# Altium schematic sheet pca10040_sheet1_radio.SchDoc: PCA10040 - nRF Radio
size A4; Revision: 1.1.0; SheetNumber: 1; SheetTotal: 5; DrawnBy: KJP; ProjectNumber: 4397; PCBRevision: 0071KJP; DocumentSize: A4; PCAName: PCA10040; PCBNumber: 400150
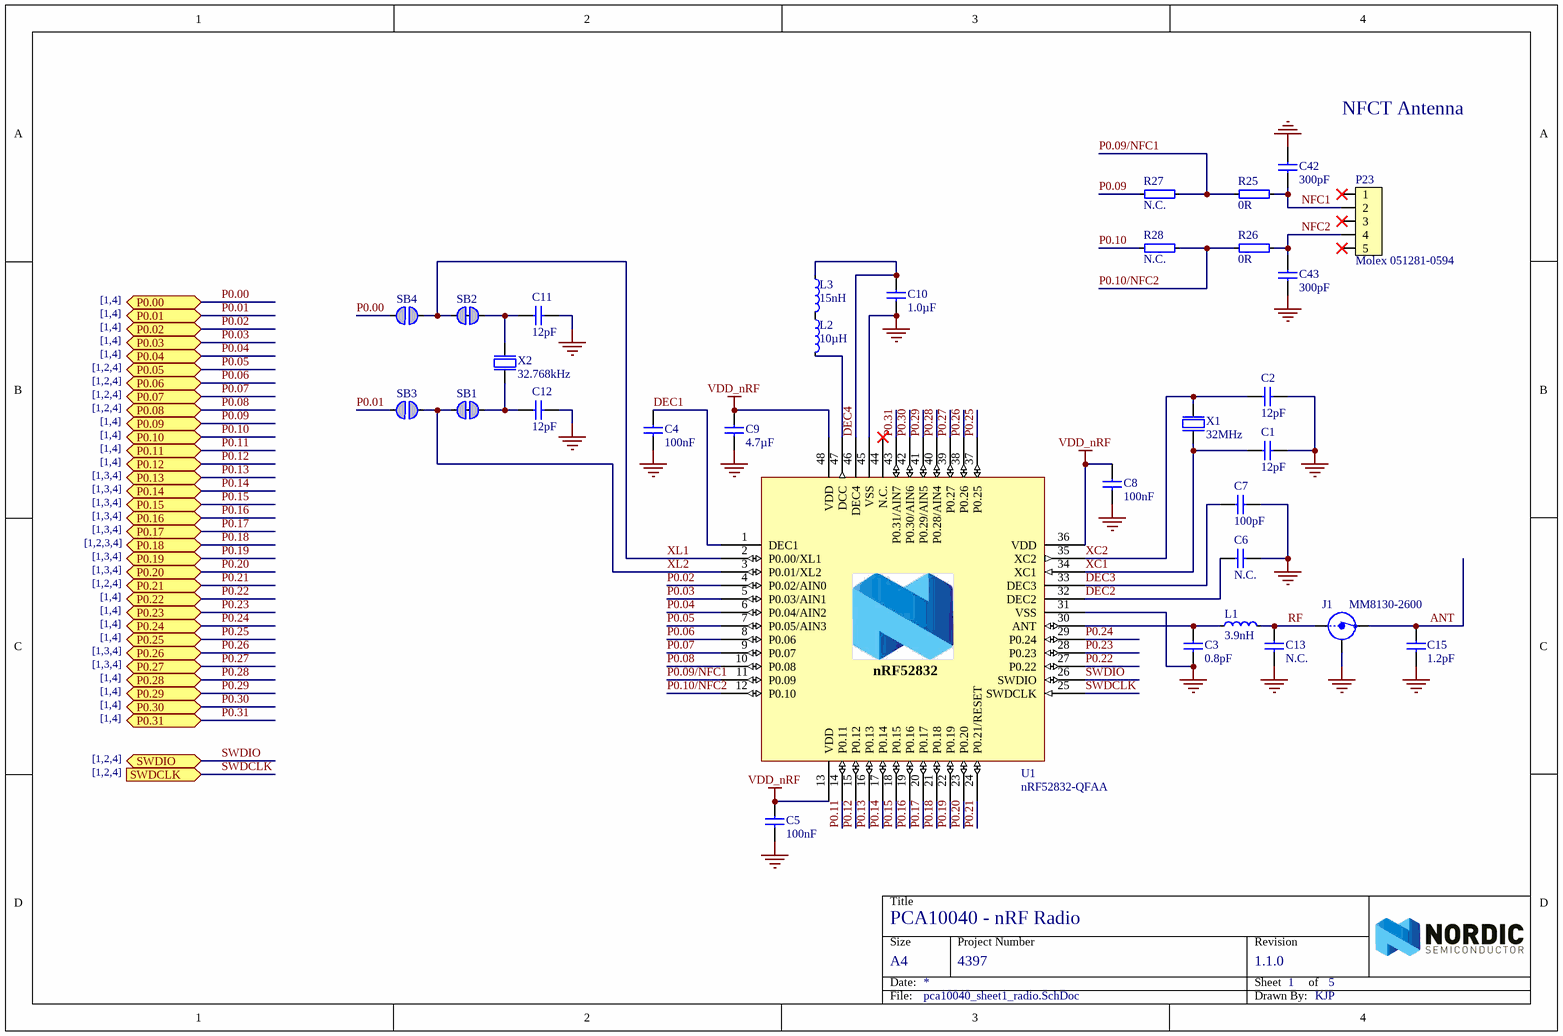
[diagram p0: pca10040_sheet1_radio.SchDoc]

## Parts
C1  12pF  [CAPC1005X04L]
C2  12pF  [CAPC1005X04L]
C3  0.8pF  [CAPC1005X04L]
C4  100nF  [CAPC1005X04L]
C5  100nF  [CAPC1005X04L]
C6  N.C.  [CAPC1005X04L]
C7  100pF  [CAPC1005X04L]
C8  100nF  [CAPC1005X04L]
C9  4.7µF  [CAPC1608X06L]
C10  1.0µF  [CAPC1608X06L]
C11  12pF  [CAPC1005X04L]
C12  12pF  [CAPC1005X04L]
C13  N.C.  [CAPC1005X04L]
C15  1.2pF  [CAPC1005X04L]
C42  300pF  [CAPC1005X04L]
C43  300pF  [CAPC1005X04L]
J1  MM8130-2600  [COAXIAL-SWF]
L1  3.9nH  [INDC1005X04L]
L2  10µH  [INDC1608X06L]
L3  15nH  [INDC1005X04L]
P23  Molex 051281-0594  [Molex 051281-0594]
R25  0R  [RESC1005X04L]
R26  0R  [RESC1005X04L]
R27  N.C.  [RESC1005X04L]
R28  N.C.  [RESC1005X04L]
SB1  Solderbridge  [Solderbridge_Shorted]  (value not drawn)  (net tie, no BOM)
SB2  Solderbridge  [Solderbridge_Shorted]  (value not drawn)  (net tie, no BOM)
SB3  Solderbridge  [Solderbridge]  (value not drawn)  (no BOM)
SB4  Solderbridge  [Solderbridge]  (value not drawn)  (no BOM)
U1  nRF52832-QFAA  [QFN40P600X600X90-48N]
X1  32MHz  [BT-XTAL_2016]
X2  32.768kHz  [XTAL_3215]

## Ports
P0.00 (bidir), P0.01 (bidir), P0.02 (bidir), P0.03 (bidir), P0.04 (bidir), P0.05 (bidir), P0.06 (bidir), P0.07 (bidir), P0.08 (bidir), P0.09 (bidir), P0.10 (bidir), P0.11 (bidir), P0.12 (bidir), P0.13 (bidir), P0.14 (bidir), P0.15 (bidir), P0.16 (bidir), P0.17 (bidir), P0.18 (bidir), P0.19 (bidir), P0.20 (bidir), P0.21 (bidir), P0.22 (bidir), P0.23 (bidir), P0.24 (bidir), P0.25 (bidir), P0.26 (bidir), P0.27 (bidir), P0.28 (bidir), P0.29 (bidir), P0.30 (bidir), P0.31 (bidir), SWDCLK (in), SWDIO (bidir)

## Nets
GND: C1.2 C2.2 C3.1 C4.2 C5.2 C6.2 C7.2 C8.2 C9.2 C10.1 C11.1 C12.1 C13.2 C15.2 C42.2 C43.1 J1.2(Shield) U1.31(VSS) U1.45(VSS) U1.49(GND) X1.2(GND) X1.4(GND)
VDD_nRF: C5.1 C8.1 C9.1 U1.13(VDD) U1.36(VDD) U1.48(VDD)
ANT: C15.1 J1.3(OUT)
DEC1: C4.1 U1.1(DEC1)
DEC2: C6.1 U1.32(DEC2)
DEC3: C7.1 U1.33(DEC3)
DEC4: C10.2 L3.1 U1.46(DEC4)
NFC1: C42.1 P23.2 R25.1
NFC2: C43.2 P23.4 R26.1
P0.00: SB4.2 ; port P0.00
P0.01: SB3.2 ; port P0.01
P0.02: U1.4(P0.02/AIN0) ; port P0.02
P0.03: U1.5(P0.03/AIN1) ; port P0.03
P0.04: U1.6(P0.04/AIN2) ; port P0.04
P0.05: U1.7(P0.05/AIN3) ; port P0.05
P0.06: U1.8(P0.06) ; port P0.06
P0.07: U1.9(P0.07) ; port P0.07
P0.08: U1.10(P0.08) ; port P0.08
P0.09: R27.1 ; port P0.09
P0.09/NFC1: R25.2 R27.2 U1.11(P0.09)
P0.10: R28.1 ; port P0.10
P0.10/NFC2: R26.2 R28.2 U1.12(P0.10)
P0.11: U1.14(P0.11) ; port P0.11
P0.12: U1.15(P0.12) ; port P0.12
P0.13: U1.16(P0.13) ; port P0.13
P0.14: U1.17(P0.14) ; port P0.14
P0.15: U1.18(P0.15) ; port P0.15
P0.16: U1.19(P0.16) ; port P0.16
P0.17: U1.20(P0.17) ; port P0.17
P0.18: U1.21(P0.18) ; port P0.18
P0.19: U1.22(P0.19) ; port P0.19
P0.20: U1.23(P0.20) ; port P0.20
P0.21: U1.24(P0.21/RESET) ; port P0.21
P0.22: U1.27(P0.22) ; port P0.22
P0.23: U1.28(P0.23) ; port P0.23
P0.24: U1.29(P0.24) ; port P0.24
P0.25: U1.37(P0.25) ; port P0.25
P0.26: U1.38(P0.26) ; port P0.26
P0.27: U1.39(P0.27) ; port P0.27
P0.28: U1.40(P0.28/AIN4) ; port P0.28
P0.29: U1.41(P0.29/AIN5) ; port P0.29
P0.30: U1.42(P0.30/AIN6) ; port P0.30
P0.31: U1.43(P0.31/AIN7) ; port P0.31
RF: C13.1 J1.1(IN) L1.2
SWDCLK: U1.25(SWDCLK) ; port SWDCLK
SWDIO: U1.26(SWDIO) ; port SWDIO
XC1: C1.1 U1.34(XC1) X1.1(inp)
XC2: C2.1 U1.35(XC2) X1.3(out)
XL1: SB2.2 SB4.1 U1.2(P0.00/XL1)
XL2: SB1.2 SB3.1 U1.3(P0.01/XL2)
NetC3_2: C3.2 L1.1 U1.30(ANT)
NetC11_2: C11.2 SB2.1 X2.1(inp)
NetC12_2: C12.2 SB1.1 X2.2(out)
NetL2_1: L2.1 L3.2
NetL2_2: L2.2 U1.47(DCC)

Not connected (* = marked no-connect by the designer): P23 1* 3* 5*; U1 44(N.C.)*

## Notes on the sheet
- NFCT Antenna
- [1,4]
- [1,2,4]
- [1,3,4]
- [1,2,3,4]

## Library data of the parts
C1 C2 C11 C12 = C0402-12p: Capacitor, NP0, ±2%; Note: 50V; Artikkelnr Noca: 20029159; Artikkelnr Simpro: N.A.
C3 = C0402-0.8p: Capacitor, NP0, ±5%; Note: 50V; Artikkelnr Noca: 20029147; Artikkelnr Simpro: N.A.
C4 C5 C8 = C0402-100n: Capacitor, X7R, ±10%; Note: 16V; Artikkelnr Noca: 20039200; Artikkelnr Simpro: N.A.
C6 C13 = C0402-N.C.: Not mounted; Note: Chip Cap; Artikkelnr Noca: N.A.
C7 = C0402-100p: Capacitor, NP0, ±5%; Note: 50V; Artikkelnr Noca: 20029135; Artikkelnr Simpro: N.A.
C9 = C0603-4µ7: Capacitor, X5R, ±10%; Note: 6.3V; Artikkelnr Noca: 20069060; Artikkelnr Simpro: N.A.
C10 = C0603-1µ0: Capacitor, X7R, ±10%; Note: 16V; Artikkelnr Noca: 20039335; Artikkelnr Simpro: N.A.
C15 = C0402-1.2p: Capacitor, NP0, ±0.1pF; Note: 50V; Artikkelnr Noca: 20029157; Artikkelnr Simpro: N.A.
C42 C43 = C0402-300p: Capacitor, NP0, ±5%; Note: 50V; Artikkelnr Noca: N.A.
J1 = MM8130-2600: Coaxial Connector with Switch; Manufacturer: Murata; 2nd source part number: 81-MM8130-2600RA2; Artikkelnr Noca: 55029011; Artikkelnr Simpro: N.A.
L1 = L0402-3n9: Inductor, 170mA, ±0.1nH; Manufacturer: Murata; Manufacturer Part Number: LQP15MN3N9B02D; Note: High frequency chip inductor ±5%; Artikkelnr Noca: 33029151; Artikkelnr Simpro: N.A.
L2 = L0603-10µ: Inductor, 80mA, ±10%; Manufacturer: Taiyo Yuden; Manufacturer Part Number: LBMF1608T100K; 2nd source part number: 178-6105; Note: LBMF1608T100K 10µH 80mA 0603; Artikkelnr Noca: 33029314; Artikkelnr Simpro: N.A.
L3 = L0402-15n: Inductor, 320mA, ±5%; Manufacturer: Taiyo Yuden; Manufacturer Part Number: HK100515NJ-T; 2nd source part number: 658-1328; Note: High frequency chip inductor ±10%; Artikkelnr Noca: 33029323; Artikkelnr Simpro: N.A.
P23 = Molex 051281-0594: CONN FFC FPC 5POS 0.50MM R/A; Artikkelnr Noca: N.A.
R25 R26 = R0402-0R: Resistor, ±5%, 0.063W; Note: Chip Res 5%; Artikkelnr Noca: 27049000; Artikkelnr Simpro: N.A.
R27 R28 = R0402-N.C.: Not mounted; Note: Chip Res; Artikkelnr Noca: N.A.
SB1 SB2 = Solderbridge Shorted: Shorted Solderbridge; Artikkelnr Noca: N.A.
SB3 SB4 = Solderbridge: Artikkelnr Noca: N.A.
U1 = nRF52832-QFAA: Multi-protocol Bluetooth Low Energy and 2.4GHz proprietary system-on-chip; Manufacturer: Nordic Semiconductor; Artikkelnr Noca: N.A.
X1 = XTAL_SMD2016_32MHz_8pF_Epson: XTAL SMD 2016, 32MHz, Cl=8pF, Tol: ±10ppm, Stab: ±10ppm; Manufacturer: Epson Toyocom; Manufacturer Part Number: Q22FA12800025; Note: XTAL SMD 32.000MHz; Artikkelnr Noca: N.A.
X2 = XTAL_FC-135 32.768k: EPSON TOYOCOM - FC-135 32.768KHZ ±20PPM,9.0PF - CRYSTAL, SM, WATCH; 2nd source part number: 127-8037; Note: XTAL SMD 32.768kHz, 3215; Artikkelnr Noca: 22019091; Artikkelnr Simpro: N.A.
